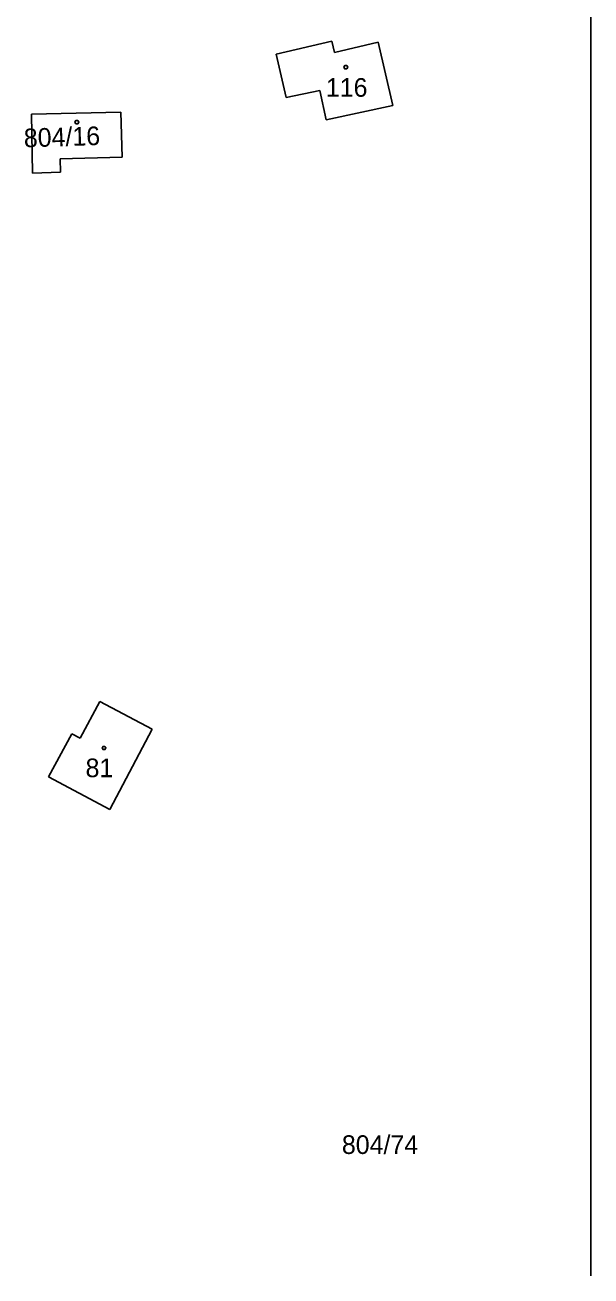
# Model space of a CAD drawing. Extents: x -852001 to -842497, y -1063614 to -1052182.
# Drawn here: x -843801.6 to -843750, y -1061500 to -1061386 of the extents above; entities that cross this region are included whole.
import ezdxf

# ---------------------------------------------------------------- set-up
doc = ezdxf.new("R2010")
doc.units = 0
for name, color, linetype in [('Default', 7, 'Continuous'), ('KLADY_ZMVM', 7, 'Continuous'), ('KN_HRANICE', 7, 'Continuous'), ('KN_KULTURY', 7, 'Continuous'), ('KN_PARCELY', 7, 'Continuous')]:
    doc.layers.add(name, color=color, linetype=linetype)

# ---------------------------------------------------------------- blocks, each defined once
blk = doc.blocks.new('402')
at = {"layer": 'Default'}
blk.add_lwpolyline([(0.09, 0.15), (0.18, 0), (0.09, -0.15), (-0.09, -0.15), (-0.18, 0), (-0.09, 0.15), (0.09, 0.15)], dxfattribs=at)

msp = doc.modelspace()

# ---------------------------------------------------------------- linework, layer by layer
at = {"layer": 'KLADY_ZMVM'}
msp.add_line((-843750, -1061000), (-843750, -1061500), dxfattribs=at)
at = {"layer": 'KN_HRANICE'}
for p, q in [((-843778.7, -1061388.64), (-843773.62, -1061387.46)), ((-843778.7, -1061388.64), (-843773.62, -1061387.46)), ((-843773.38, -1061388.48), (-843773.62, -1061387.46)), ((-843773.38, -1061388.48), (-843773.62, -1061387.46)), ((-843769.39, -1061387.54), (-843773.38, -1061388.48)), ((-843769.39, -1061387.54), (-843773.38, -1061388.48)), ((-843769.39, -1061387.54), (-843768.05, -1061393.32)), ((-843769.39, -1061387.54), (-843768.05, -1061393.32)), ((-843778.7, -1061388.64), (-843777.77, -1061392.61)), ((-843778.7, -1061388.64), (-843777.77, -1061392.61)), ((-843774.7, -1061391.95), (-843777.77, -1061392.61)), ((-843774.7, -1061391.95), (-843777.77, -1061392.61)), ((-843774.12, -1061394.63), (-843774.7, -1061391.95)), ((-843774.12, -1061394.63), (-843774.7, -1061391.95)), ((-843801, -1061394.11), (-843792.85, -1061393.92)), ((-843801, -1061394.11), (-843792.85, -1061393.92)), ((-843801, -1061394.11), (-843800.88, -1061399.48)), ((-843801, -1061394.11), (-843800.88, -1061399.48)), ((-843792.85, -1061393.92), (-843792.73, -1061398.04)), ((-843792.85, -1061393.92), (-843792.73, -1061398.04)), ((-843768.05, -1061393.32), (-843774.12, -1061394.63)), ((-843768.05, -1061393.32), (-843774.12, -1061394.63)), ((-843792.73, -1061398.04), (-843798.36, -1061398.2)), ((-843792.73, -1061398.04), (-843798.36, -1061398.2)), ((-843798.36, -1061398.2), (-843798.33, -1061399.41)), ((-843798.36, -1061398.2), (-843798.33, -1061399.41)), ((-843798.33, -1061399.41), (-843800.88, -1061399.48)), ((-843798.33, -1061399.41), (-843800.88, -1061399.48)), ((-843794.77, -1061447.65), (-843796.56, -1061450.99)), ((-843794.77, -1061447.65), (-843796.56, -1061450.99)), ((-843789.99, -1061450.16), (-843794.77, -1061447.65)), ((-843789.99, -1061450.16), (-843794.77, -1061447.65)), ((-843793.84, -1061457.48), (-843789.99, -1061450.16)), ((-843793.84, -1061457.48), (-843789.99, -1061450.16)), ((-843799.45, -1061454.51), (-843797.31, -1061450.58)), ((-843799.45, -1061454.51), (-843797.31, -1061450.58)), ((-843796.56, -1061450.99), (-843797.31, -1061450.58)), ((-843796.56, -1061450.99), (-843797.31, -1061450.58)), ((-843793.84, -1061457.48), (-843799.45, -1061454.51)), ((-843793.84, -1061457.48), (-843799.45, -1061454.51))]:
    msp.add_line(p, q, dxfattribs=at)

# ---------------------------------------------------------------- block references
at = {"layer": 'KN_KULTURY'}
for p in [(-843772.35, -1061389.84), (-843772.35, -1061389.84), (-843796.85, -1061394.84), (-843796.85, -1061394.84), (-843794.38, -1061451.88), (-843794.38, -1061451.88)]:
    msp.add_blockref('402', p, dxfattribs=at)

# ---------------------------------------------------------------- texts
at = {"layer": 'KN_PARCELY'}
for s, p in [('116', (-843774.16, -1061392.53)), ('116', (-843774.16, -1061392.53)), ('81', (-843796.06, -1061454.54)), ('81', (-843796.06, -1061454.54)), ('804/74', (-843772.7, -1061488.88)), ('804/74', (-843772.7, -1061488.88))]:
    msp.add_text(s, height=1.7, dxfattribs=at).set_placement(p)
msp.add_text('804/16', height=1.7, rotation=1.776, dxfattribs=at).set_placement((-843801.66, -1061397.14))
msp.add_text('804/16', height=1.7, rotation=1.776, dxfattribs=at).set_placement((-843801.66, -1061397.14))

doc.saveas('drawing.dxf')
